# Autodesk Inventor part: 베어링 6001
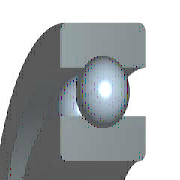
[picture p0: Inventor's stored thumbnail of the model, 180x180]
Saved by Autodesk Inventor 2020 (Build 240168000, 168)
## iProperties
Created: 2012-02
Part Number: 베어링 6001
Material: 강철, 연강
Description: 깊은 그루브 볼 베어링
Document SubType Name: Modeling
Standard: KS B 2023
Designer: mduedu
Standards Organization: KS
Language: ko-KR
Size Designation: 6001 - 12 x 28 x 8
Categories: <MemberInstance><Categories><Category DisplayName="샤프트 부품" InternalName="7f7aeb1f-a693-4053-b835-cee3144e0d98" Mnemonic="SHFT"><Category DisplayName="베어링" Inter
Density: 7.86 g/cm^3
Mass: 21.4855 g
Surface Area: 31.1809 cm^2
Volume: 2.73352 cm^3
Appearance: 노란색
IsCustomPart: 1
Author: mduedu
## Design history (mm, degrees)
sketch "스케치" dims "d0" = 4.16 (= -0.26 x WD + 0.26 x BD)
  geometry: L1 (1.92, 10)-(6.08, 10); L2 (4, 10)-(4, 7.92); L3 (4, 10)-(4, 12.08); L4 (2.454, 8.608)-(0, 8.608); L5 (0, 6)-(8, 6); L6 (2.454, 11.392)-(0, 11.392); L7 (0, 14)-(8, 14); L8 (8, 6)-(8, 8.608); L9 (5.546, 8.608)-(8, 8.608); L10 (5.546, 11.392)-(8, 11.392); L11 (8, 14)-(8, 11.392); L12 (-1.4, 0)-(8.4, 0) reference; L13 (0, -0.3)-(0, 5.3) reference
  constraints: 22 end point, 4 point on line, 2 collinear, 2 perpendicular, 2 symmetric about line, 1 midpoint, 1 parallel, 14 other
  dimensions: "d9" = 12 diameter of L5 L12 (= WD); "d11" = 28 diameter of L7 L12 (= BD); "d12" = 8 distance between parallel lines of L8 L13 (= KB); "d13" = 17.216 diameter of L9 L12 (= 0.326 x BD + 0.674 x WD)
revolve "본체" stored, may be unused: angle "d6" = 90 deg
revolve "볼" stored, may be unused: angle "d7" = 90 deg
pattern_circular "IDS_ARRAYBALL[SIMPL:T]" dims angle "d3" = 360 deg
body "Solid1"
fillet "모깎기1" dims "d1" = 0.3 (= KRS)
other parameters: "WD" = 12 [user parameter; used in 5 equation terms], "BD" = 28 [user parameter; used in 5 equation terms], "KB" = 8 [user parameter; used in 1 equation term], "KRS" = 0.3 [user parameter; used in 1 equation term], "d4" = 0, "d5" = 0, "d8" = 0, "d14" = 0, "d15" = 0, "BBA" = 0 [user parameter], "BC0" = 2360000 [user parameter], "BC" = 5070000 [user parameter], "BR" = 14 (= 0.5 x BD) [user parameter], "WR" = 6 (= 0.5 x WD) [user parameter]
